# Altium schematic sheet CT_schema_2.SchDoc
size 276 x 169 mm
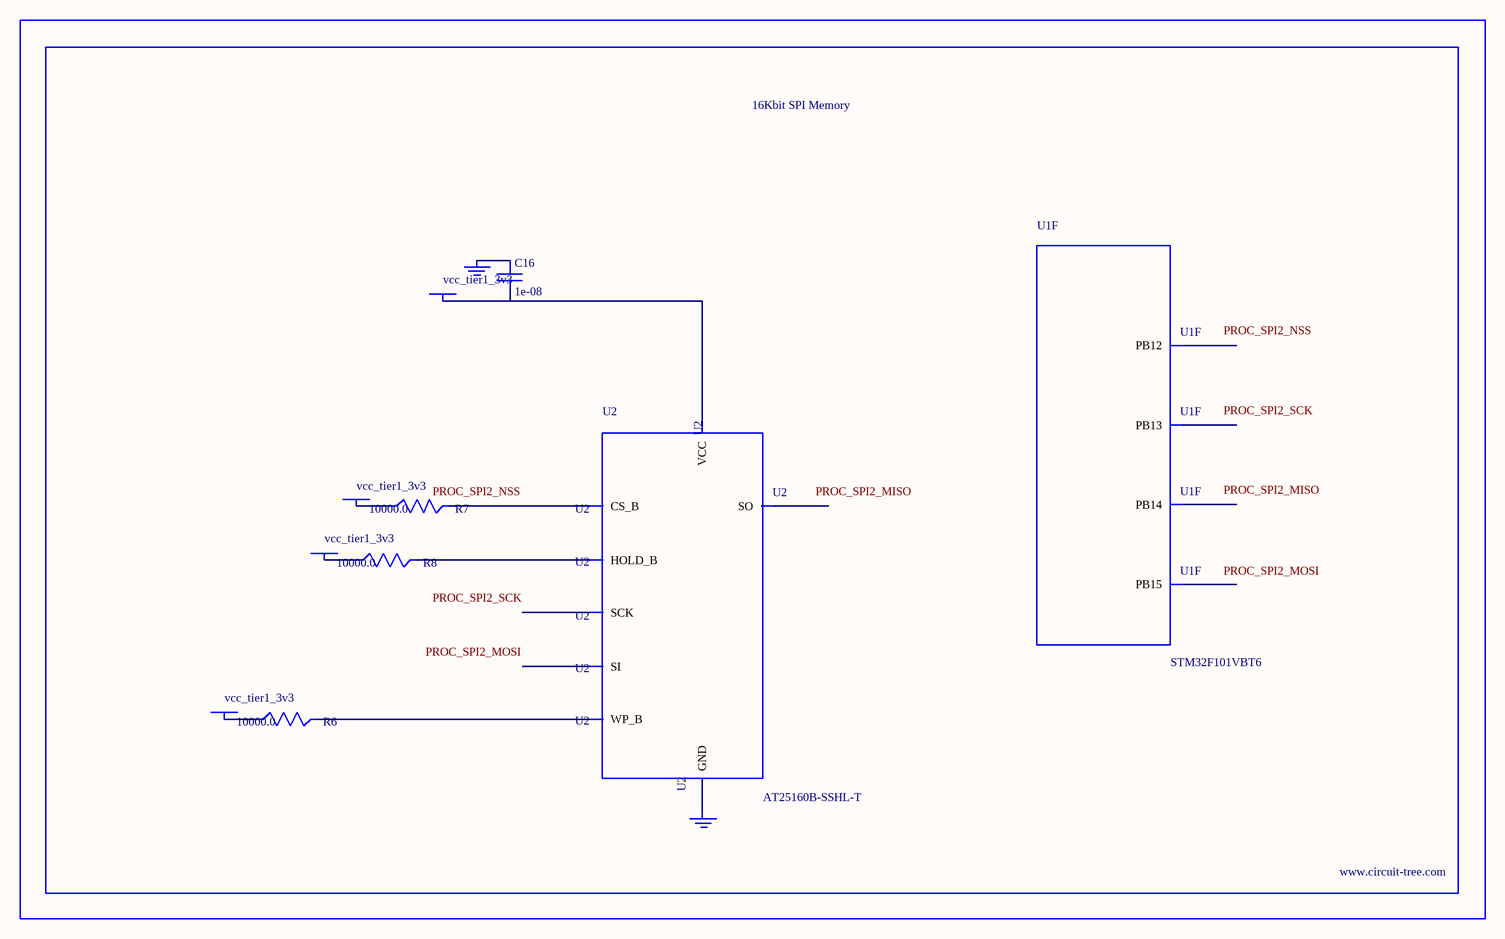
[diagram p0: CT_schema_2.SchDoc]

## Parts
BORDER1  (no value)
C16  1e-08  [C0402]
GND_INSTANCE_1_0  (no value)
GND_INSTANCE_1_1  (no value)
POWER_INSTANCE_1_0  vcc_tier1_3v3
POWER_INSTANCE_1_1  vcc_tier1_3v3
POWER_INSTANCE_1_2  vcc_tier1_3v3
POWER_INSTANCE_1_3  vcc_tier1_3v3
R6  10000.0  [R0603]
R7  10000.0  [R0603]
R8  10000.0  [R0603]
U1  STM32F101VBT6  [LQFP100]  (part F of 9)
U2  AT25160B-SSHL-T  [SOIC-8]

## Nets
NetC16_1: C16.1 GND_INSTANCE_1_0.0(GND)
NetC16_2: C16.2 POWER_INSTANCE_1_3.0(PWR) U2.8(VCC)
NetGND_INSTANCE_1_1_0: GND_INSTANCE_1_1.0(GND) U2.4(GND)
NetPOWER_INSTANCE_1_0_0: POWER_INSTANCE_1_0.0(PWR) R7.1
NetPOWER_INSTANCE_1_1_0: POWER_INSTANCE_1_1.0(PWR) R6.1
NetPOWER_INSTANCE_1_2_0: POWER_INSTANCE_1_2.0(PWR) R8.1
NetR6_2: R6.2 U2.3(WP_B)
NetR7_2: R7.2 U2.1(CS_B)
NetR8_2: R8.2 U2.7(HOLD_B)

Not connected (* = marked no-connect by the designer): U1 51(PB12) 52(PB13) 53(PB14) 54(PB15); U2 2(SO) 5(SI) 6(SCK)

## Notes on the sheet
- Labels drawn without touching a wire or pin: PROC_SPI2_MISO, PROC_SPI2_MOSI, PROC_SPI2_NSS, PROC_SPI2_SCK

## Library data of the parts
BORDER1 = BORDER_PAGE1
C16 = C0402C103K3RAC
GND_INSTANCE_1_0 GND_INSTANCE_1_1 = GND
POWER_INSTANCE_1_0-POWER_INSTANCE_1_3 = PWR
R6-R8 = RC0603JR-0710KL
